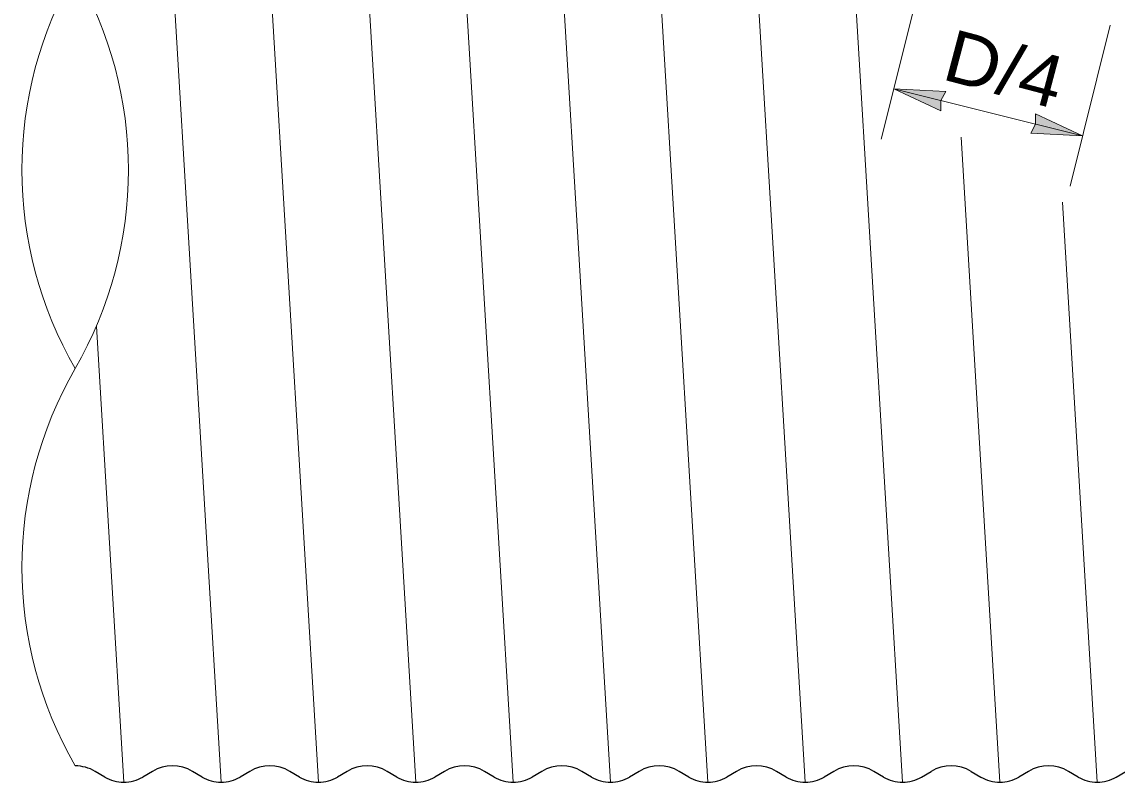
# Model space of a CAD drawing. Extents: x 99860 to 103153, y 99998 to 102077.
# Drawn here: x 100599.7 to 100937.3, y 101551.1 to 101785.5 of the extents above; entities that cross this region are included whole.
import ezdxf
from ezdxf.enums import TextEntityAlignment as Align

# ---------------------------------------------------------------- set-up
doc = ezdxf.new("R2010")
doc.units = 0
doc.header["$LTSCALE"] = 6.4
for name, color, linetype, lineweight in [('1', 7, 'Continuous', 13), ('15', 7, 'Continuous', 13), ('20', 7, 'Continuous', 13)]:
    doc.layers.add(name, color=color, linetype=linetype, lineweight=lineweight)

msp = doc.modelspace()

# ---------------------------------------------------------------- hatches: boundary and pattern name
at = {"layer": '1'}
msp.add_hatch(color=256, dxfattribs=at).paths.add_polyline_path([(100926.635, 101750.387), (100910.632, 101751.209), (100912.086, 101754.024), (100912.128, 101757.193)])
at = {"layer": '15'}
msp.add_hatch(color=256, dxfattribs=at).paths.add_polyline_path([(100868.427, 101764.939), (100882.934, 101758.133), (100882.976, 101761.302), (100884.43, 101764.117)])

# ---------------------------------------------------------------- linework, layer by layer
at = {"layer": '1'}
for p, q in [((100661.12, 101551.125), (100646.12, 101801.125)), ((100691.12, 101551.125), (100676.12, 101801.125)), ((100721.12, 101551.125), (100706.12, 101801.125)), ((100751.12, 101551.125), (100736.12, 101801.125)), ((100781.12, 101551.125), (100766.12, 101801.125)), ((100811.12, 101551.125), (100796.12, 101801.125)), ((100841.12, 101551.125), (100826.12, 101801.125)), ((100871.12, 101551.125), (100856.12, 101801.125)), ((100901.12, 101551.125), (100889.185, 101750.042)), ((100931.12, 101551.125), (100920.394, 101729.902)), ((100631.12, 101551.125), (100622.683, 101691.749))]:
    msp.add_line(p, q, dxfattribs=at)
at = {"layer": '1', "lineweight": 25}
for p, q in [((100639.982, 101554.439), (100636.995, 101552.662)), ((100655.246, 101552.662), (100652.259, 101554.439)), ((100669.982, 101554.439), (100666.995, 101552.662)), ((100685.246, 101552.662), (100682.259, 101554.439)), ((100699.982, 101554.439), (100696.995, 101552.662)), ((100715.246, 101552.662), (100712.259, 101554.439)), ((100729.982, 101554.439), (100726.995, 101552.662)), ((100745.246, 101552.662), (100742.259, 101554.439)), ((100759.982, 101554.439), (100756.995, 101552.662)), ((100775.246, 101552.662), (100772.259, 101554.439)), ((100789.982, 101554.439), (100786.995, 101552.662)), ((100805.246, 101552.662), (100802.259, 101554.439)), ((100819.982, 101554.439), (100816.995, 101552.662)), ((100835.246, 101552.662), (100832.259, 101554.439)), ((100849.982, 101554.439), (100846.995, 101552.662)), ((100865.246, 101552.662), (100862.259, 101554.439)), ((100876.995, 101552.662), (100879.982, 101554.439)), ((100892.259, 101554.439), (100895.246, 101552.662)), ((100909.982, 101554.439), (100906.995, 101552.662)), ((100925.246, 101552.662), (100922.259, 101554.439)), ((100936.995, 101552.662), (100939.982, 101554.439))]:
    msp.add_line(p, q, dxfattribs=at)
at = {"layer": '1'}
msp.add_lwpolyline([(100926.635, 101750.387), (100910.632, 101751.209), (100912.086, 101754.024), (100912.128, 101757.193)], close=True, dxfattribs=at)
at = {"layer": '1', "lineweight": 25}
msp.add_lwpolyline([(100625.246, 101552.662), (100622.259, 101554.439), (100622.258, 101554.437)], dxfattribs=at)
at = {"layer": '1'}
for centre, start, end in [((100722.209, 101739.875), 150, 210), ((100510.032, 101739.875), 330, 30), ((100722.209, 101617.375), 150, 210)]:
    msp.add_arc(centre, 122.5, start, end, dxfattribs=at)
at = {"layer": '1', "lineweight": 25}
for centre, start, end in [((100616.12, 101544.125), 59.24007, 90), ((100646.12, 101544.125), 59.24007, 120.75993), ((100676.12, 101544.125), 59.24007, 120.75993), ((100706.12, 101544.125), 59.24007, 120.75993), ((100736.12, 101544.125), 59.24007, 120.75993), ((100766.12, 101544.125), 59.24007, 120.75993), ((100796.12, 101544.125), 59.24007, 120.75993), ((100826.12, 101544.125), 59.24007, 120.75993), ((100856.12, 101544.125), 59.24007, 120.75993), ((100886.12, 101544.125), 59.24007, 120.75992), ((100916.12, 101544.125), 59.24007, 120.75993), ((100631.12, 101563.125), 240.68709, 270), ((100631.12, 101563.125), 270, 299.31291), ((100661.12, 101563.125), 240.68709, 270), ((100661.12, 101563.125), 270, 299.31291), ((100691.12, 101563.125), 240.68709, 270), ((100691.12, 101563.125), 270, 299.31291), ((100721.12, 101563.125), 240.68709, 270), ((100721.12, 101563.125), 270, 299.31291), ((100751.12, 101563.125), 240.68709, 270), ((100751.12, 101563.125), 270, 299.31291), ((100781.12, 101563.125), 240.68709, 270), ((100781.12, 101563.125), 270, 299.31291), ((100811.12, 101563.125), 240.68709, 270), ((100811.12, 101563.125), 270, 299.31291), ((100841.12, 101563.125), 240.68709, 270), ((100841.12, 101563.125), 270, 299.31291), ((100871.12, 101563.125), 240.68709, 270), ((100871.12, 101563.125), 270, 299.31291), ((100901.12, 101563.125), 240.68709, 270), ((100901.12, 101563.125), 270, 299.31291), ((100931.12, 101563.125), 240.68709, 270), ((100931.12, 101563.125), 270, 299.31291)]:
    msp.add_arc(centre, 12, start, end, dxfattribs=at)
at = {"layer": '15'}
for p, q in [((100876.951, 101799.036), (100864.547, 101749.42)), ((100935.16, 101784.483), (100922.756, 101734.868)), ((100926.635, 101750.387), (100868.427, 101764.939))]:
    msp.add_line(p, q, dxfattribs=at)
msp.add_lwpolyline([(100868.427, 101764.939), (100882.934, 101758.133), (100882.976, 101761.302), (100884.43, 101764.117)], close=True, dxfattribs=at)

# ---------------------------------------------------------------- texts
at = {"layer": '20', "width": 1.1}
msp.add_text('D/4', height=16, rotation=345.208, dxfattribs=at).set_placement((100900.473, 101763.308), align=Align.CENTER)

doc.saveas('drawing.dxf')
